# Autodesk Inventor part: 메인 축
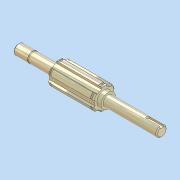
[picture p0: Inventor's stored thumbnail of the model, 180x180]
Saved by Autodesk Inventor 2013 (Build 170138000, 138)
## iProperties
Company: 한국ATC센터
Created: 2014-07
Part Number: 메인 축
Document SubType Name: 모델링
Designer: KYOUNG IL JANG
Mass: 21.4461 g
Surface Area: 72.5104 cm^2
Volume: 21.4461 cm^3
Density: 1 g/cm^3
Material: Generic
변환 표준: STEP AP214IS
파일 이름: C:\Users\SeoGD\Desktop\?쒗뿕\硫붿씤 異?.stp
전처리기: Build: 253, Release: 2010 SP1 - Date: Wed 07/29/2009
전송 단위: 밀리미터
불확실성: 0.01
Author: KYOUNG IL JANG
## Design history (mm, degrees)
revolve "회전1" stored, may be unused: angle "d10" = 90 deg
sketch "스케치2"
  geometry: L1 (2.5, 10.712)-(2.5, 8.646); L2 (-2.5, 10.712)-(-2.5, 8.646); A1 r 9 centre (0, 0) between (2.5, 8.646) and (-2.5, 8.646) reference; A2 r 11 centre (0, 0) between (2.5, 10.712) and (-2.5, 10.712); 1 further point
  constraints: 4 end point, 4 point on circle, 2 parallel, 1 centre point, 1 coincident, 1 vertical
  dimensions: "d11" = 22 diameter of A2; "d12" = 5 distance between parallel lines of L1 L2
extrude "돌출1" join sketch "스케치2" stored distance "d13" = 10; taper "d14" = 0 deg
chamfer "모따기1" distance "d15" = 1; stored, may be unused: second distance "d16" = 2, angle "d17" = 45 deg
node "작업 평면1"
node "작업 평면2"
sketch "스케치3"
  geometry: L1 (2.5, 10.712)-(2.5, 10.198); L2 (-2.5, 10.712)-(-2.5, 10.198); A1 r 11 centre (0, 0) between (2.5, 10.712) and (-2.5, 10.712) reference; A2 r 10.5 centre (0, 0) between (2.5, 10.198) and (-2.5, 10.198); 1 further point
  constraints: 4 end point, 2 point on circle, 1 centre point, 1 coincident, 1 parallel, 1 vertical
  dimensions: "d19" = 21 diameter of A2
extrude "돌출2" cut sketch "스케치3" distance "d20" = 1.35; taper "d21" = 0 deg
node "작업 평면3"
sketch "스케치4"
  geometry: L1 (-26, -5)-(-26, 5) reference; L2 (-26, 1.5)-(-12.5, 1.5); L3 (-12.5, -1.5)-(-26, -1.5); A1 r 1.5 centre (-12.5, 0) between (-12.5, -1.5) and (-12.5, 1.5); 2 further points
  constraints: 4 end point, 2 perpendicular, 2 point on circle, 2 point on line, 2 tangent, 1 centre point, 1 horizontal alignment, 1 midpoint
  dimensions: "d25" = 3 distance between parallel lines of L3 L2; "d26" = 15 dimension on A1 L1
extrude "돌출3" cut sketch "스케치4" distance "d27" = 1.8; taper "d28" = 0 deg
chamfer "모따기2" distance "d29" = 1; stored, may be unused: second distance "d30" = 2, angle "d31" = 45 deg
node "솔리드1"
node "솔리드 본체"
node "곡면 본체"
mirror "대칭1"
pattern_circular "원형 패턴1" dims "d23" = 360 deg
sketch "스케치1"
  geometry: L1 (-69.5, 0)-(69.5, 0); L2 (69.5, 0)-(69.5, 5); L3 (69.5, 5)-(55.5, 5); L4 (55.5, 5)-(55.5, 4.8); L5 (55.5, 4.8)-(54.35, 4.8); L6 (54.35, 4.8)-(54.35, 5); L7 (54.35, 5)-(30.5, 5); L8 (30.5, 5)-(30.5, 9); L9 (30.5, 9)-(-13.5, 9); L10 (-13.5, 9)-(-13.5, 7); L11 (-13.5, 7)-(-17.5, 7); L12 (-17.5, 7)-(-17.5, 5); L13 (-17.5, 5)-(-69.5, 5); L14 (-69.5, 5)-(-69.5, 0); 2 further points
  constraints: 28 end point, 9 parallel, 4 collinear, 2 perpendicular, 1 coincident, 1 horizontal, 1 midpoint
  dimensions: "d2" = 1.15 distance between parallel lines of L6 L4; "d3" = 10 diameter of L3 L1; "d4" = 9.6 diameter of L5 L1; "d6" = 44 distance between parallel lines of L10 L8; "d7" = 4 distance between parallel lines of L12 L10; "d8" = 14 diameter of L11 L1; "d9" = 18 diameter of L9 L1; "d33" = 52 distance from line of L12.end L14; "d37" = 39 distance between parallel lines of L8 L2; "d38" = 14 distance between parallel lines of L2 L4
node "솔리드2"
other parameters: "d18" = -1.65
